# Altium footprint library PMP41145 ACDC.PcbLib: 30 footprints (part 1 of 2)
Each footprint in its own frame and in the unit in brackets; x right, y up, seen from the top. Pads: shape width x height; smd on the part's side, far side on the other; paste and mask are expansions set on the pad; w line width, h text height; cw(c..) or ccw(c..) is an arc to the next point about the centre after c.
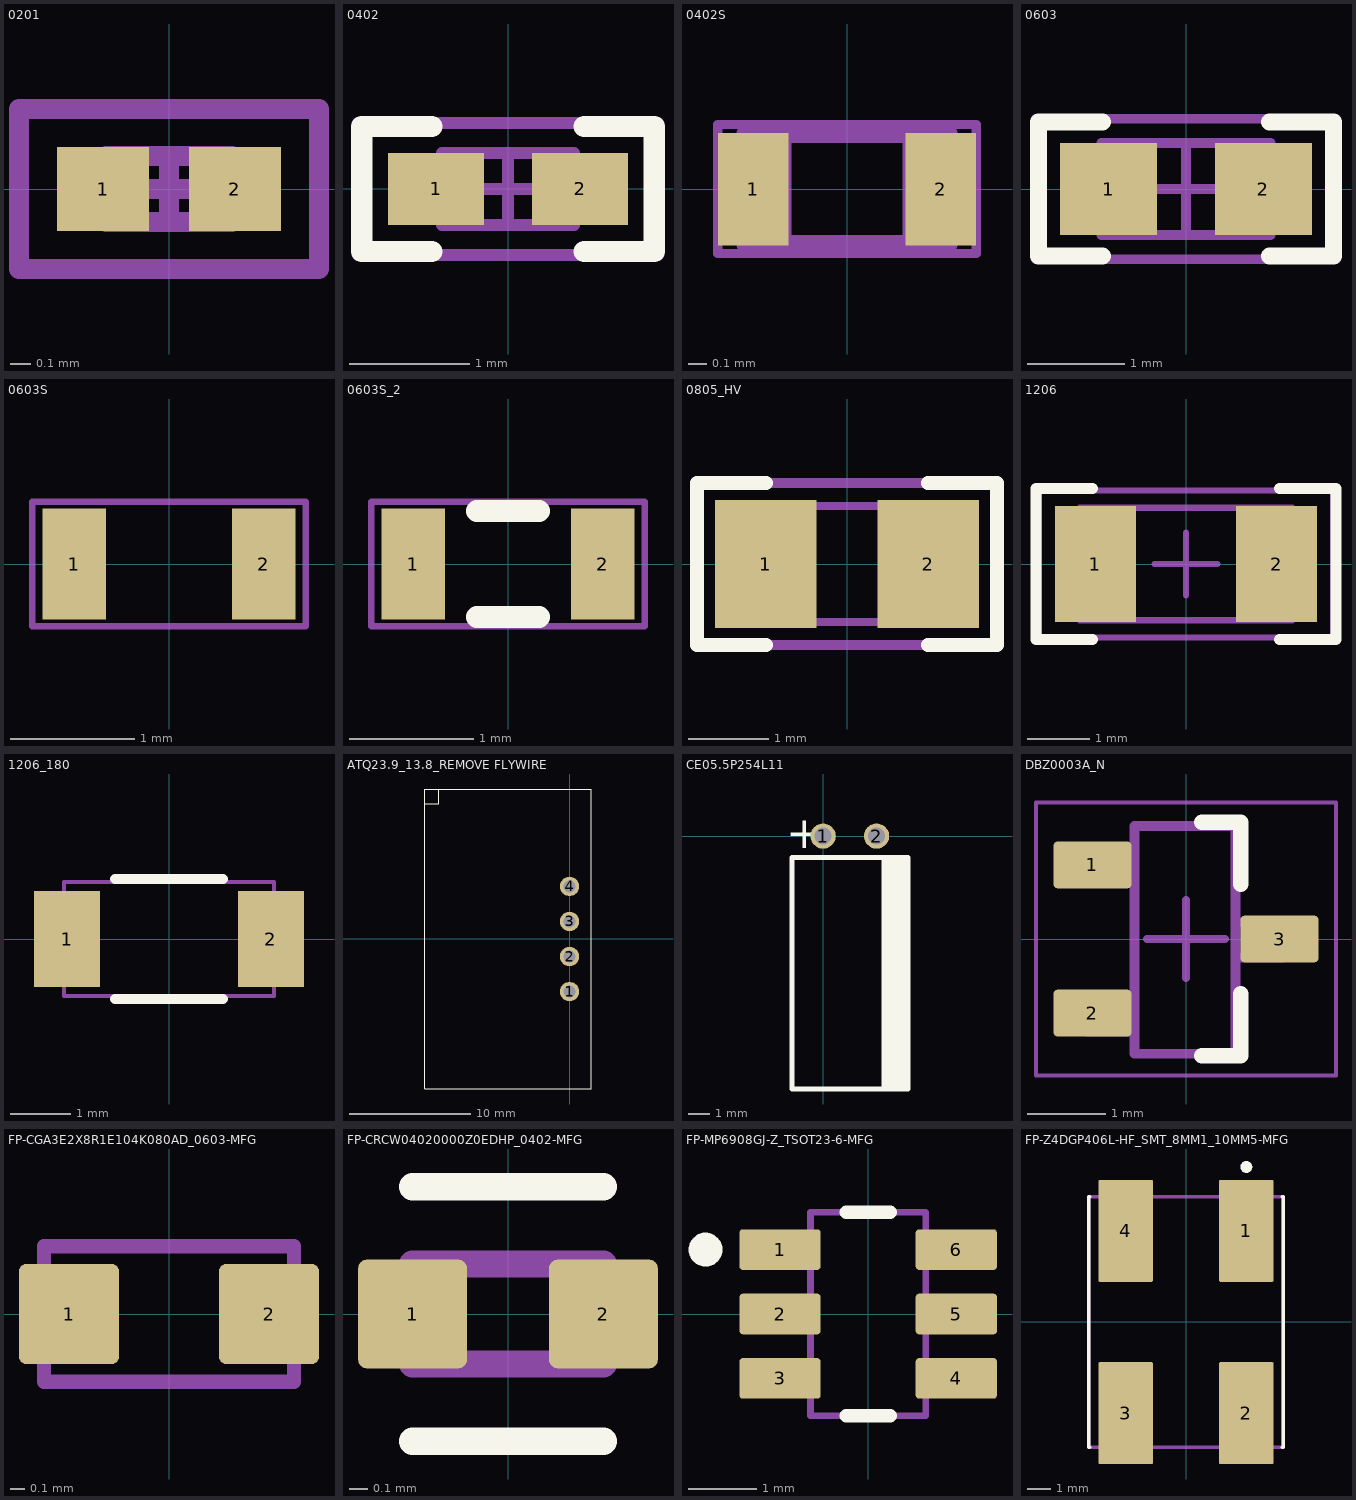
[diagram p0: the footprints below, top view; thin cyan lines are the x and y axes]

## 0201 [mm] "Data from Kemet datasheet CC101_COM dated 7/28/11"
height 0.26
pads (2):
  rect 0.46x0.42 smd mask+0.048: 1(-0.33,0) 2(0.33,0)
Mechanical 5:
  lines w0.1: -0.75,-0.4 -0.75,0.4 0.75,0.4 0.75,-0.4 -0.75,-0.4
  text ".Designator" at -0.66,-0.178 h0.36
Mechanical 13:
  lines w0.1: -0.215,-0.165 -0.215,0.165 ; 0.215,-0.165 0.215,0.165 ; -0.315,-0.165 0.315,-0.165 0.315,0.165 -0.315,0.165 -0.315,-0.165
Mechanical 15:
  lines w0.1: -0.165,0 0.165,0 ; 0,-0.165 0,0.165 ; -0.75,-0.4 0.75,-0.4 0.75,0.4 -0.75,0.4 -0.75,-0.4
3D body: height 0.26, standoff 0, extent 0.216,-0.164 0.314,0.164
3D body: height 0.26, standoff 0, extent -0.214,-0.164 0.214,0.164
3D body: height 0.26, standoff 0, extent -0.314,-0.164 -0.216,0.164

## 0402 [mm] "0402 from SM-752 data"
height 0.6
pads (2):
  rect 0.8x0.6 smd: 1(-0.6,0) 2(0.6,0)
Top Overlay:
  lines w0.178: -0.635,-0.521 -1.219,-0.521 -1.219,0.521 -0.635,0.521 ; 0.635,-0.521 1.219,-0.521 1.219,0.521 0.635,0.521
Mechanical 5:
  lines w0.1: -1.25,-0.55 1.25,-0.55 1.25,0.55 -1.25,0.55 -1.25,-0.55
  text ".Designator" at -1.117,-0.305 h0.61
Mechanical 13:
  lines w0.1: -0.35,-0.3 -0.35,0.3 ; 0.35,-0.3 0.35,0.3 ; -0.55,-0.3 -0.55,0.3 0.55,0.3 0.55,-0.3 -0.55,-0.3
Mechanical 15:
  lines w0.1: -0.3,0 0.3,0 ; 0,-0.3 0,0.3 ; -1.25,-0.55 -1.25,0.55 1.25,0.55 1.25,-0.55 -1.25,-0.55
3D body: height 0.6, standoff 0, extent -0.549,-0.299 -0.351,0.299
3D body: height 0.6, standoff 0, extent -0.349,-0.299 0.349,0.299
3D body: height 0.6, standoff 0, extent 0.351,-0.299 0.549,0.299

## 0402S [mil] "Based on C0402S footprint from PADS legacy"
height 23.62
pads (2):
  rect 15x24 smd: 1(-20,0) 2(20,0)
Mechanical 5:
  lines w1.97: -27.56,-13.78 -27.56,13.78 27.56,13.78 27.56,-13.78 -27.56,-13.78
  text ".Designator" at -21.65,-5.91 h12
Mechanical 13:
  lines w3.94: -13.78,-11.81 -13.78,11.81 ; 13.78,-11.81 13.78,11.81 ; -21.65,-11.81 21.65,-11.81 21.65,11.81 -21.65,11.81 -21.65,-11.81
3D body: height 23.62, standoff 0, extent 13.8,-11.79 21.63,11.79
3D body: height 23.62, standoff 0, extent -13.76,-11.79 13.76,11.79
3D body: height 23.62, standoff 0, extent -21.63,-11.79 -13.8,11.79

## 0603 [mm] "0603 from SM-752 data"
height 1
pads (2):
  rect 1x0.95 smd: 1(-0.8,0) 2(0.8,0)
Top Overlay:
  lines w0.178: -0.864,-0.691 -1.524,-0.691 -1.524,0.693 -0.864,0.693 ; 0.864,-0.691 1.524,-0.691 1.524,0.693 0.864,0.693
Mechanical 5:
  lines w0.1: -1.55,-0.725 -1.55,0.725 1.55,0.725 1.55,-0.725 -1.55,-0.725
  text ".Designator" at -1.397,-0.381 h0.76
Mechanical 13:
  lines w0.1: -0.55,-0.475 -0.55,0.475 ; 0.55,-0.475 0.55,0.475 ; -0.875,-0.475 0.875,-0.475 0.875,0.475 -0.875,0.475 -0.875,-0.475
Mechanical 15:
  lines w0.1: -0.475,0 0.475,0 ; 0,-0.475 0,0.475 ; -1.55,-0.725 1.55,-0.725 1.55,0.725 -1.55,0.725 -1.55,-0.725
3D body: height 1, standoff 0, extent -0.874,-0.474 -0.551,0.474
3D body: height 1, standoff 0, extent -0.549,-0.474 0.549,0.474
3D body: height 1, standoff 0, extent 0.551,-0.474 0.874,0.474

## 0603S [mil]
height 39.37
pads (2):
  rect 20x35 smd: 1(-30,0) 2(30,0)
Mechanical 5:
  lines w1.97: -43.31,-19.68 43.31,-19.68 43.31,19.68 -43.31,19.68 -43.31,-19.68
  text ".Designator" at -32.48,-8.86 h18
3D body: height 39.37, standoff 0, extent -34.43,-18.68 -21.67,18.68
3D body: height 39.37, standoff 0, extent -21.63,-18.68 21.63,18.68
3D body: height 39.37, standoff 0, extent 21.67,-18.68 34.43,18.68

## 0603S_2 [mil]
pads (2):
  rect 20x35 smd: 1(-30,0) 2(30,0)
Top Overlay:
  lines w7: -9.84,-16.73 9.84,-16.73 ; -9.84,16.73 9.84,16.73
Mechanical 5:
  lines w1.97: -43.31,-19.68 -43.31,19.68 43.31,19.68 43.31,-19.68 -43.31,-19.68
  text ".Designator" at -32.48,-8.86 h18
3D body: height 39.37, standoff 0, extent 21.67,-18.68 34.43,18.68
3D body: height 39.37, standoff 0, extent -21.63,-18.68 21.63,18.68
3D body: height 39.37, standoff 0, extent -34.43,-18.68 -21.67,18.68

## 0805_HV [mil] "0805 with 30mil clearance between pads"
height 57.09
pads (2):
  rect 50x63 smd: 1(-40,0) 2(40,0)
Top Overlay:
  lines w7: -40,-40 -74,-40 -74,0 -74,40 -40,40 ; 40,-40 74,-40 74,0 74,40 40,40
Mechanical 5:
  lines w5: -74,-40 74,-40 74,40 -74,40 -74,-40
  text ".Designator" at -64,-17 h35
Mechanical 13:
  lines w3.94: -25.59,-28.54 -25.59,28.54 ; 25.59,-28.54 25.59,28.54 ; -43.31,-28.54 43.31,-28.54 43.31,28.54 -43.31,28.54 -43.31,-28.54
3D body: height 57.09, standoff 0, extent 25.61,-28.52 43.29,28.52
3D body: height 57.09, standoff 0, extent -43.29,-28.52 -25.61,28.52
3D body: height 57.09, standoff 0, extent -25.57,-28.52 25.57,28.52

## 1206 [mm] "1206 from SM-752 data"
height 1.35
pads (2):
  rect 1.3x1.85 smd: 1(-1.45,0) 2(1.45,0)
Top Overlay:
  lines w0.178: -1.5,-1.21 -2.4,-1.21 -2.4,1.21 -1.5,1.21 ; 1.5,-1.21 2.4,-1.21 2.4,1.21 1.5,1.21
Mechanical 5:
  lines w0.1: -1.7,-0.9 -1.7,0.9 1.7,0.9 1.7,-0.9 -1.7,-0.9
  text ".Designator" at -1.475,-0.4 h0.81
Mechanical 13:
  lines w0.1: -1.2,-0.9 -1.2,0.9 ; 1.2,-0.9 1.2,0.9 ; -1.7,-0.9 -1.7,0.9 1.7,0.9 1.7,-0.9 -1.7,-0.9
Mechanical 15:
  lines w0.1: -0.5,0 0.5,0 ; 0,-0.5 0,0.5 ; -2.35,-1.175 -2.35,1.175 2.35,1.175 2.35,-1.175 -2.35,-1.175
3D body: height 1.35, standoff 0, extent 1.201,-0.899 1.699,0.899
3D body: height 1.35, standoff 0, extent -1.199,-0.899 1.199,0.899
3D body: height 1.35, standoff 0, extent -1.699,-0.899 -1.201,0.899

## 1206_180 [mm] "1206_180"
height 1.8
pads (2):
  rect 1.1x1.6 smd: 1(-1.7,0) 2(1.7,0)
Top Overlay:
  lines w0.17: -0.9,-1 0.9,-1 ; -0.9,1 0.9,1
Mechanical 5:
  lines w0.07: -1.75,-0.95 1.75,-0.95 1.75,0.95 -1.75,0.95 -1.75,-0.95
  text ".Designator" at -1.5,-0.4 h0.81
3D body: height 1.8, standoff 0, extent -1.749,-0.949 -1.301,0.949
3D body: height 1.8, standoff 0, extent -1.299,-0.949 1.299,0.949
3D body: height 1.8, standoff 0, extent 1.301,-0.949 1.749,0.949

## ATQ23.9_13.8_REMOVE FLYWIRE [mm]
pads (4):
  round 1.6 hole 1: 1(0,-4.35) 2(0,-1.45) 3(0,1.45) 4(0,4.35)
Top Overlay:
  lines w0.1: -11.978,11.192 -10.819,11.192 -10.819,12.367 ; -11.988,-12.4 1.812,-12.4 1.812,12.4 -11.988,12.4 -11.988,-12.4

## CE05.5P254L11 [mm]
pads (2):
  round 1.2 hole 0.8: 1(0,0) 2(2.54,0)
Top Overlay:
  rectangle: 2.784,-12.016 4.02,-1.016
  lines w0.254: -1.48,-12.016 -1.48,-1.016 4.02,-1.016 4.02,-12.016 -1.48,-12.016
  text "+" at -1.753,0.737 h1.5
Bottom Overlay:
  circle w0.2: c2.54,0 r0.85
  lines w0.2: -0.849,-0.85 -0.849,0.849 0.849,0.849 0.849,-0.85 -0.849,-0.85

## DBZ0003A_N [mm] "SOT23, 3-Leads, Body 2.9x1.3mm, Pitch 0.95mm, Lead Span 2.4mm, IPC Medium Density"
height 1.12
pads (3):
  rrect17% 1x0.6 smd: 1(-1.2,0.95) 2(-1.2,-0.95) 3(1.2,0)
Top Overlay:
  lines w0.2: 0.2,-1.5 0.7,-1.5 0.7,-0.7 ; 0.2,1.5 0.7,1.5 0.7,0.7
Mechanical 5:
  lines w0.127: -1.27,-1.187 -1.27,-0.743 -1.063,-0.743 -1.005,-0.743 -0.814,-0.743 -0.66,-0.743 -0.66,-1.187 -0.814,-1.187 -1.005,-1.187 -1.063,-1.187 -1.27,-1.187 ; -1.27,0.718 -1.27,1.162 -1.063,1.162 -1.005,1.162 -0.814,1.162 -0.66,1.162 -0.66,0.718 -0.814,0.718 -1.005,0.718 -1.063,0.718 -1.27,0.718 ; -0.66,-1.473 -0.66,1.448 0.635,1.448 0.635,-1.473 -0.66,-1.473 ; 0.635,-0.235 0.789,-0.235 0.98,-0.235 1.037,-0.235 1.245,-0.235 1.245,0.21 1.037,0.21 0.98,0.21 0.789,0.21 0.635,0.21 0.635,-0.235
  text ".Designator" at -0.254,0.889 h0.51
Mechanical 15:
  lines w0.05: -1.925,-1.75 1.925,-1.75 1.925,1.75 -1.925,1.75 -1.925,-1.75
  lines w0.1: -0.5,0 0.5,0 ; 0,-0.5 0,0.5
3D body "DBZ0003A.stp": height 0.98, standoff 0, extent -1.257,-1.46 1.257,1.461

## FP-CGA3E2X8R1E104K080AD_0603-MFG [mm]
height 0.7
pads (2):
  rrect14% 0.7x0.7 smd paste+0 mask+0: 1(-0.7,0) 2(0.7,0)
Mechanical 5:
  lines w0.1: -0.875,-0.475 0.875,-0.475 0.875,0.475 -0.875,0.475 -0.875,-0.475
  text ".Designator" at 0,0 h0.5
3D body "Cap_CGA3E2X8R1E104K080AD_0603.STEP": height 0.95, standoff 0, extent -0.8,-0.4 0.8,0.4

## FP-CRCW04020000Z0EDHP_0402-MFG [mm]
pads (2):
  rrect17% 0.6x0.6 smd paste+0 mask+0: 1(-0.525,0) 2(0.525,0)
Top Overlay:
  lines w0.15: -0.525,-0.7 0.525,-0.7 ; -0.525,0.7 0.525,0.7
Mechanical 5:
  lines w0.15: -0.525,-0.275 0.525,-0.275 0.525,0.275 -0.525,0.275 -0.525,-0.275
  text ".Designator" at 0.05,0.217 h0.5
3D body "Res_CRCW04020000Z0EDHP_0402.STEP": height 0.4, standoff 0, extent -0.5,-0.25 0.5,0.25

## FP-MP6908GJ-Z_TSOT23-6-MFG [mm]
height 0.7
pads (6):
  rrect17% 1.2x0.6 smd paste+0 mask+0: 1(-1.3,0.95) 2(-1.3,0) 3(-1.3,-0.95) 4(1.3,-0.95) 5(1.3,0) 6(1.3,0.95)
Top Overlay:
  circle w0.25: c-2.4,0.95 r0.125
  lines w0.2: -0.325,-1.5 0.325,-1.5 ; -0.325,1.5 0.325,1.5
Mechanical 5:
  lines w0.1: -0.85,-1.5 0.85,-1.5 0.85,1.5 -0.85,1.5 -0.85,-1.5
  text ".Designator" at 0,0 h0.5
3D body "IC_MP6908GJ-Z_TSOT23-6.STEP": height 1, standoff 0, extent -1.4,-1.45 1.4,1.45

## FP-Z4DGP406L-HF_SMT_8MM1_10MM5-MFG [mm]
height 0.7
pads (4):
  rrect4% 2.3x4.3 smd paste+0 mask+0: 1(2.55,3.85) 2(2.55,-3.85) 3(-2.55,-3.85) 4(-2.55,3.85)
Top Overlay:
  circle w0.25: c2.55,6.55 r0.125
  lines w0.15: -4.075,-5.3 -4.1,-5.3 -4.1,5.3 -4.075,5.3 ; 4.075,-5.3 4.1,-5.3 4.1,5.3 4.075,5.3
Mechanical 5:
  lines w0.15: -4.1,-5.3 4.1,-5.3 4.1,5.3 -4.1,5.3 -4.1,-5.3
  text ".Designator" at 0.05,0.217 h0.5
3D body "Diode_Z4DGP406L-HF_SMT_8MM1_10MM5.STEP": height 1.45, standoff 0, extent -4.05,-5.25 4.05,5.25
